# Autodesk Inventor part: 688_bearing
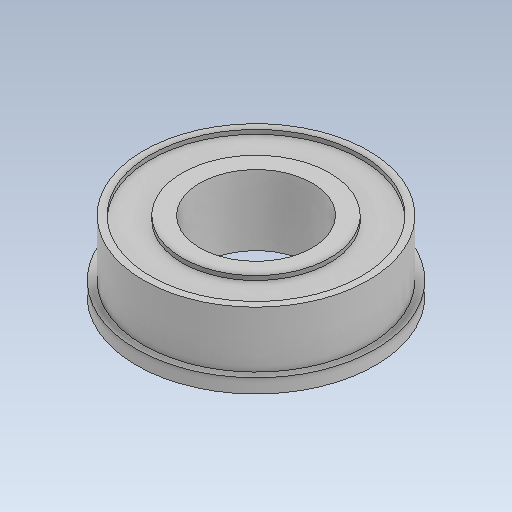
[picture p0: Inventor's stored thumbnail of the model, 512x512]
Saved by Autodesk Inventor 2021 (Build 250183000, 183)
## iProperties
Created: 2026-10
Part Number: 688_bearing
Material: Generic
Document SubType Name: Modeling
Designer: hp
Density: 1 g/cm^3
Appearance: Default
Author: hp
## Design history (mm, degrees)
feature "Body1"
body "Solid1"
